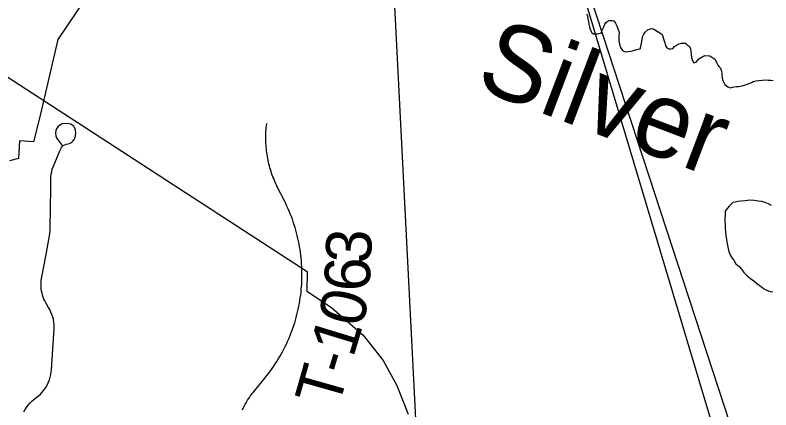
# Model space of a CAD drawing. Extents: x -11.4 to 84.1, y 11.1 to 59.
# Drawn here: x 29.748 to 30.691, y 42.977 to 43.47 of the extents above; entities that cross this region are included whole.
import ezdxf

# ---------------------------------------------------------------- set-up
doc = ezdxf.new("R2010")
doc.units = 0
for name, color, linetype in [('GM_X_Corporation', 7, 'Continuous'), ('GM_X_Minor_Lake', 7, 'Continuous'), ('GM_X_Minor_River', 7, 'Continuous'), ('GM_X_Minor_River_Text', 7, 'Continuous'), ('GM_X_Township_Road', 7, 'Continuous'), ('GM_X_Township_Road_Text', 7, 'Continuous'), ('SH_Data', 7, 'Continuous')]:
    doc.layers.add(name, color=color, linetype=linetype)

msp = doc.modelspace()

# ---------------------------------------------------------------- linework, layer by layer
at = {"layer": 'GM_X_Corporation'}
for points in [[(30.24767, 42.96585), (30.20088, 43.89052), (30.17852, 43.90074), (30.16108, 43.90814), (30.14406, 43.91644), (30.14069, 43.91591), (30.0978, 43.93683), (30.11717, 43.57845), (30.00085, 43.58666), (30.01955, 43.85142), (30.01808, 43.85261), (30.01694, 43.88966), (29.99211, 43.89093), (29.9955, 43.99162), (30.01908, 43.98274), (30.03898, 44.29872), (29.90846, 44.30515), (29.88919, 44.02828), (29.78066, 44.07203), (29.77816, 44.03029), (29.68366, 44.03885)], [(29.74026, 43.89651), (29.79173, 43.89119), (29.93862, 43.8783), (29.93676, 43.86015), (30.08829, 43.85), (30.06198, 43.60198), (30.0298, 43.60387), (29.91204, 43.61041), (29.90576, 43.59589), (29.90424, 43.57749), (29.89398, 43.5783), (29.80092, 43.43935), (29.77834, 43.34299), (29.77049, 43.31191), (29.75316, 43.31301), (29.75207, 43.29087), (29.74064, 43.28811)], [(29.34531, 43.6481), (30.11202, 43.14996), (30.11178, 43.12523), (30.14245, 43.10478), (30.18213, 43.0705), (30.20678, 43.03863), (30.22422, 43.00735), (30.23805, 42.97187)]]:
    msp.add_lwpolyline(points, dxfattribs=at)
at = {"layer": 'GM_X_Minor_Lake'}
msp.add_lwpolyline([(30.69148, 43.23232), (30.68803, 43.23417), (30.68383, 43.236), (30.67963, 43.23707), (30.67506, 43.23776), (30.67011, 43.23844), (30.66441, 43.23872), (30.65872, 43.23825), (30.65379, 43.23779), (30.64962, 43.23734), (30.64622, 43.23652), (30.64356, 43.2361), (30.64095, 43.23339), (30.63871, 43.23146), (30.63685, 43.22877), (30.63387, 43.22529), (30.63358, 43.22034), (30.63326, 43.21654), (30.63332, 43.21274), (30.63377, 43.20856), (30.63384, 43.20438), (30.63431, 43.19906), (30.63477, 43.19451), (30.6356, 43.19034), (30.63604, 43.18655), (30.63687, 43.18238), (30.6377, 43.17859), (30.63852, 43.1748), (30.63971, 43.17177), (30.64089, 43.16913), (30.64246, 43.1665), (30.6444, 43.16387), (30.64714, 43.15935), (30.65137, 43.156), (30.65408, 43.15262), (30.65719, 43.14849), (30.66106, 43.14437), (30.66529, 43.14102), (30.66952, 43.13804), (30.67299, 43.13544), (30.67607, 43.13283), (30.67876, 43.13097), (30.68145, 43.12873), (30.68452, 43.12688), (30.68987, 43.12507), (30.6933, 43.12437)], dxfattribs=at)
at = {"layer": 'GM_X_Minor_River'}
for points in [[(30.46072, 43.47151), (30.4619, 43.46887), (30.46234, 43.46545), (30.46315, 43.46204), (30.46359, 43.45863), (30.46441, 43.45522), (30.46522, 43.45257), (30.4664, 43.44955), (30.46758, 43.44767), (30.46949, 43.44656), (30.47405, 43.44663), (30.47632, 43.44705), (30.47935, 43.44786), (30.48007, 43.45015), (30.48079, 43.45207), (30.48226, 43.45551), (30.48372, 43.45858), (30.48595, 43.46166), (30.48896, 43.46323), (30.49086, 43.46326), (30.49276, 43.46329), (30.49466, 43.46294), (30.49699, 43.45994), (30.49857, 43.45654), (30.49977, 43.45276), (30.50096, 43.45011), (30.50138, 43.44784), (30.50105, 43.44441), (30.50112, 43.44061), (30.50117, 43.43757), (30.50199, 43.43378), (30.5032, 43.42962), (30.50554, 43.42585), (30.50823, 43.42438), (30.51051, 43.42403), (30.5124, 43.42445), (30.51657, 43.42489), (30.51922, 43.4257), (30.52186, 43.4265), (30.52527, 43.42732), (30.52754, 43.42774), (30.52863, 43.4308), (30.52932, 43.43499)], [(30.52932, 43.43499), (30.53, 43.43956), (30.5307, 43.443), (30.53217, 43.44606), (30.53402, 43.44876), (30.53777, 43.45186), (30.54041, 43.45266), (30.54231, 43.45307), (30.5446, 43.45235), (30.5469, 43.45125), (30.55342, 43.44717), (30.55534, 43.44568), (30.55614, 43.44342), (30.55695, 43.44039), (30.55775, 43.43774), (30.55855, 43.43547), (30.55897, 43.43358), (30.55938, 43.43168), (30.56094, 43.42905), (30.56362, 43.42795), (30.5659, 43.42799), (30.56855, 43.42841), (30.57041, 43.43072), (30.57304, 43.43229), (30.57643, 43.43424), (30.57945, 43.43505), (30.58211, 43.43509), (30.58439, 43.43475), (30.58632, 43.43288), (30.58901, 43.43102), (30.59058, 43.42839), (30.59101, 43.42498), (30.59146, 43.4208), (30.59191, 43.417), (30.59311, 43.41322), (30.59467, 43.41059), (30.59771, 43.41102), (30.60105, 43.41525), (30.60594, 43.41838), (30.60858, 43.41956), (30.61466, 43.41928), (30.61735, 43.41742), (30.62081, 43.41482), (30.62275, 43.41219), (30.62355, 43.40992), (30.62473, 43.40728), (30.62628, 43.4054), (30.62783, 43.40352), (30.62903, 43.40012), (30.62946, 43.39747), (30.62951, 43.39443), (30.62994, 43.39139), (30.63075, 43.38836), (30.63154, 43.38647), (30.63349, 43.38347), (30.63696, 43.38048), (30.6404, 43.37902), (30.64305, 43.37982), (30.64532, 43.38024), (30.64797, 43.38066), (30.65063, 43.3807), (30.65252, 43.38112), (30.65517, 43.38154), (30.65895, 43.38274), (30.66159, 43.38393), (30.66347, 43.38472), (30.66649, 43.38591), (30.66875, 43.38709), (30.67215, 43.3879), (30.67595, 43.38834), (30.68011, 43.38879), (30.68505, 43.38925), (30.68733, 43.38891), (30.69075, 43.38859), (30.6938, 43.38826)]]:
    msp.add_lwpolyline(points, dxfattribs=at)
at = {"layer": 'GM_X_Township_Road'}
for points in [[(29.75867, 42.9745), (29.76023, 42.97741), (29.76199, 42.98021), (29.76393, 42.98286), (29.76607, 42.98539), (29.76839, 42.98776), (29.77085, 42.98996), (29.77346, 42.99196), (29.77668, 42.99452), (29.77915, 42.99676), (29.78138, 42.99917), (29.78351, 43.00174), (29.78583, 43.00512), (29.78749, 43.00799), (29.78896, 43.01095), (29.79052, 43.01478), (29.79148, 43.01795), (29.79223, 43.02117), (29.79276, 43.02443), (29.79304, 43.0272), (29.79479, 43.05277), (29.79653, 43.07833), (29.79643, 43.08328), (29.79605, 43.08657), (29.79549, 43.08983), (29.79468, 43.09304), (29.79364, 43.09618), (29.79241, 43.09924), (29.79095, 43.10221), (29.78929, 43.10508), (29.78749, 43.10785), (29.78578, 43.11082), (29.7846, 43.11314), (29.78356, 43.1155), (29.78266, 43.11792), (29.78191, 43.12037), (29.78124, 43.12287), (29.78073, 43.12541), (29.78035, 43.12795), (29.78006, 43.13138), (29.77997, 43.13396), (29.78007, 43.13654), (29.78025, 43.13911), (29.78087, 43.1433), (29.78579, 43.16885), (29.7907, 43.1944), (29.79108, 43.19769), (29.79128, 43.201), (29.79177, 43.23206), (29.79206, 43.24998), (29.79235, 43.26789), (29.79273, 43.27119), (29.7933, 43.27444), (29.79406, 43.27765), (29.79539, 43.28157), (29.8035, 43.30066), (29.80573, 43.3045), (29.80755, 43.30723), (29.80953, 43.30808), (29.81197, 43.30895), (29.81548, 43.30984), (29.81802, 43.3109), (29.81968, 43.31256), (29.82147, 43.31478), (29.82261, 43.31696), (29.82316, 43.3192), (29.82354, 43.32297), (29.82319, 43.32612), (29.8223, 43.32902), (29.82075, 43.33119), (29.8189, 43.33275), (29.81731, 43.33363), (29.8148, 43.33432), (29.81256, 43.3347), (29.80656, 43.33406), (29.80427, 43.33314), (29.80131, 43.3309), (29.79949, 43.32809), (29.79832, 43.3257), (29.79792, 43.32242), (29.79845, 43.31933), (29.79936, 43.31686), (29.80135, 43.31391), (29.80638, 43.3071)], [(30.0312, 42.97706), (30.03205, 42.97885), (30.03295, 42.98063), (30.03385, 42.98238), (30.0348, 42.98412), (30.0358, 42.98585), (30.0368, 42.98755), (30.03784, 42.98923), (30.03893, 42.99091), (30.04002, 42.99256), (30.04116, 42.99419), (30.04234, 42.9958), (30.04353, 42.99739), (30.04471, 42.99895), (30.04623, 43.0008), (30.05927, 43.0167), (30.06197, 43.02005), (30.06415, 43.02287), (30.06628, 43.02571), (30.06837, 43.0286), (30.07041, 43.03153), (30.07235, 43.03449), (30.07429, 43.03747), (30.07614, 43.0405), (30.078, 43.04356), (30.07975, 43.04665), (30.08146, 43.04976), (30.08312, 43.05291), (30.08468, 43.05609), (30.08625, 43.05928), (30.08771, 43.06252), (30.08914, 43.06577), (30.09052, 43.06906), (30.09184, 43.07235), (30.09312, 43.07569), (30.09431, 43.07902), (30.09545, 43.0824), (30.09654, 43.08579), (30.09754, 43.08919), (30.09853, 43.09261), (30.09943, 43.09605), (30.10024, 43.0995), (30.10105, 43.10297), (30.10176, 43.10646), (30.10242, 43.10995), (30.10304, 43.11345), (30.10356, 43.11697), (30.10404, 43.12049), (30.10447, 43.12402), (30.1048, 43.12756), (30.10514, 43.1311), (30.10532, 43.13465), (30.10552, 43.13821), (30.10561, 43.14176), (30.10543, 43.15597), (30.10524, 43.15953), (30.10496, 43.16307), (30.10463, 43.16661), (30.10425, 43.17014), (30.10378, 43.17367), (30.10326, 43.17719), (30.10269, 43.1807), (30.10208, 43.1842), (30.10137, 43.18768), (30.10061, 43.19115), (30.09981, 43.19463), (30.09891, 43.19806), (30.09802, 43.20149), (30.09697, 43.20491), (30.09593, 43.20831), (30.09484, 43.21168), (30.09366, 43.21503), (30.09243, 43.21838), (30.09111, 43.22168), (30.08978, 43.22498), (30.08836, 43.22824), (30.08689, 43.23148), (30.08538, 43.2347), (30.08382, 43.23789), (30.07525, 43.25486), (30.0742, 43.25702), (30.07317, 43.25919), (30.07217, 43.26137), (30.07123, 43.26357), (30.07033, 43.26579), (30.06948, 43.26803), (30.06862, 43.27028), (30.06782, 43.27254), (30.06706, 43.27482), (30.06635, 43.2771), (30.06569, 43.27941), (30.06508, 43.28173), (30.06446, 43.28404), (30.06394, 43.28638), (30.06342, 43.28872), (30.06295, 43.29108), (30.06252, 43.29344), (30.06214, 43.29581), (30.06176, 43.29818), (30.06149, 43.30056), (30.0612, 43.30294), (30.06101, 43.30533), (30.06082, 43.30771), (30.06068, 43.31012), (30.06059, 43.31251), (30.06073, 43.32449), (30.06088, 43.32689), (30.06112, 43.32928), (30.06135, 43.33166), (30.06169, 43.33448)]]:
    msp.add_lwpolyline(points, dxfattribs=at)
at = {"layer": 'SH_Data'}
msp.add_lwpolyline([(31.45018, 40.48107), (30.37199, 43.77957), (31.45018, 40.17403)], close=True, dxfattribs=at)

# ---------------------------------------------------------------- texts
at = {"layer": 'GM_X_Minor_River_Text'}
msp.add_text('Silver', height=0.094752, rotation=339.22135, dxfattribs=at).set_placement((30.31939, 43.37994))
at = {"layer": 'GM_X_Township_Road_Text'}
for s, rotation, p in [('3', 87.06898, (30.19134, 43.15911)), ('6', 87.75088, (30.18998, 43.12432)), ('0', 77.20465, (30.18074, 43.0789)), ('1', 72.98048, (30.16931, 43.04102)), ('-', 72.91792, (30.16244, 43.01865)), ('T', 74.23179, (30.15099, 42.97808))]:
    msp.add_text(s, height=0.05682, rotation=rotation, dxfattribs=at).set_placement(p)

doc.saveas('drawing.dxf')
